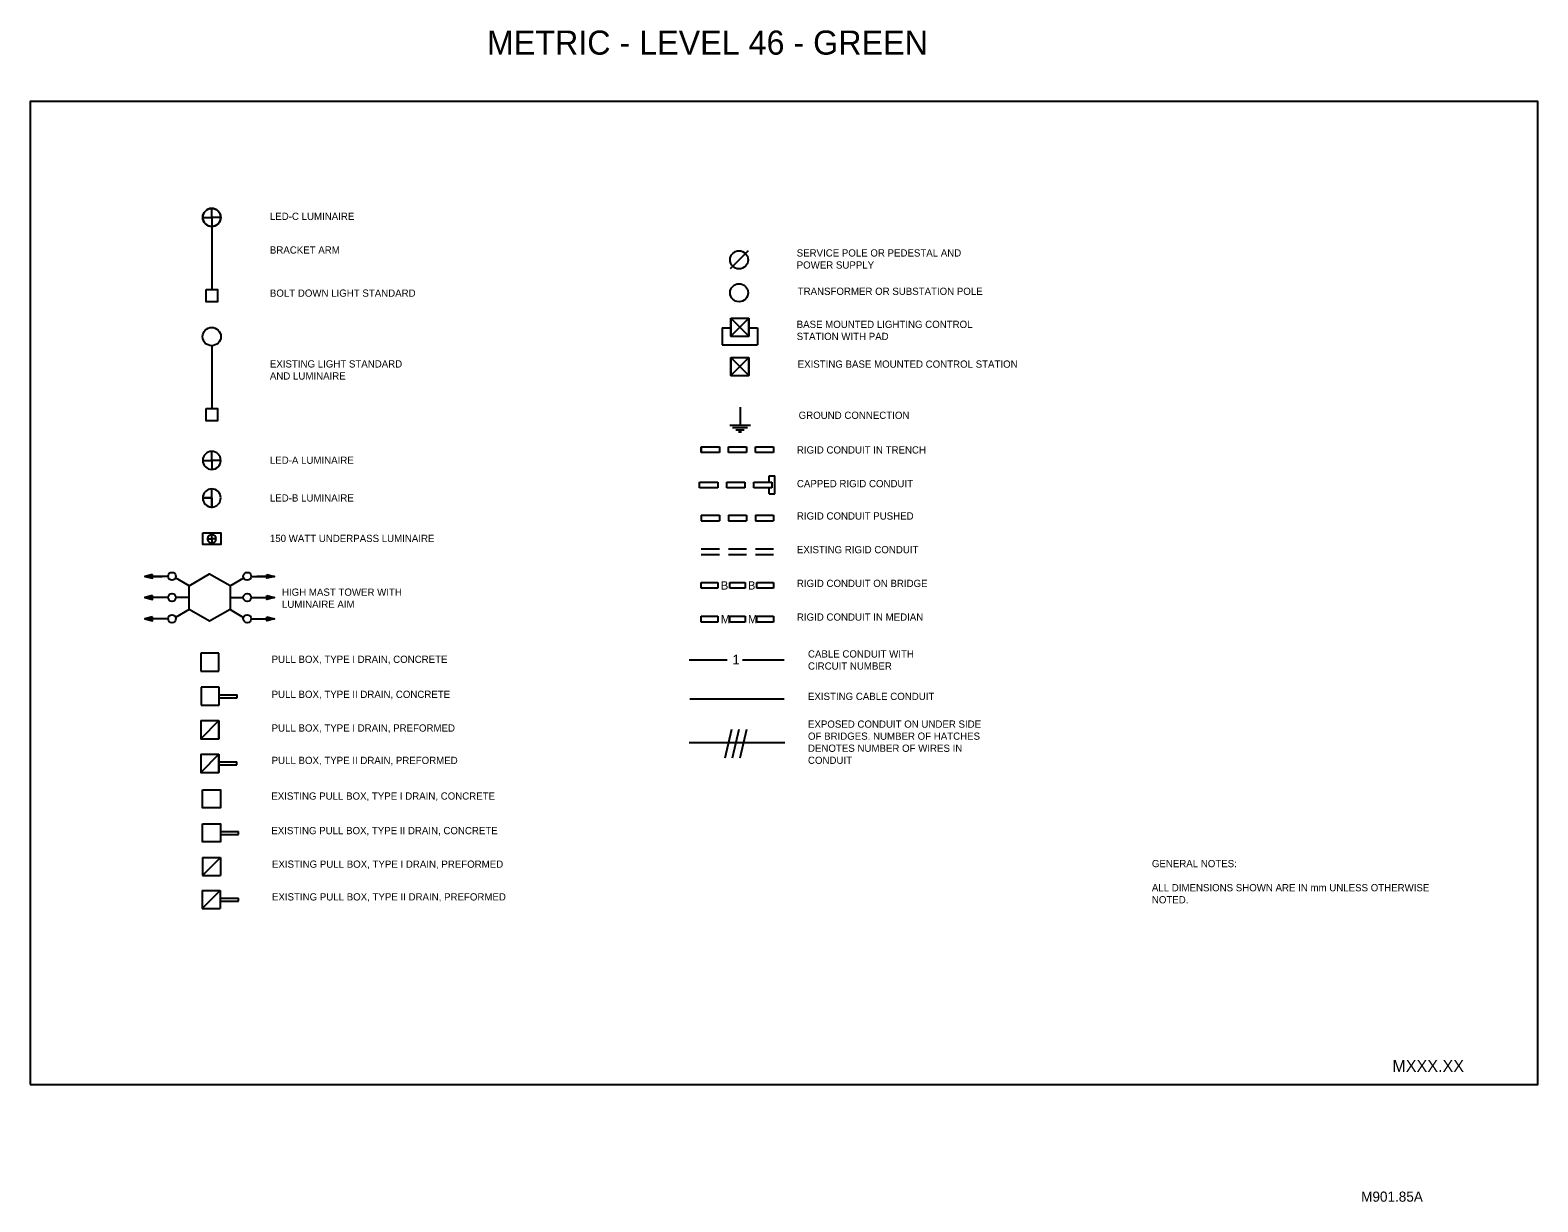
# Model space of a CAD drawing. Extents: x -439.1 to -407.9, y -460.5 to -436.2.
import ezdxf

# ---------------------------------------------------------------- set-up
doc = ezdxf.new("R2010")
doc.units = 0
for name, color, linetype in [('Draft_Named_Boundary', 7, 'Continuous'), ('Level 4', 7, 'Continuous'), ('Level 46', 7, 'Continuous')]:
    doc.layers.add(name, color=color, linetype=linetype)

msp = doc.modelspace()

# ---------------------------------------------------------------- linework, layer by layer
at = {"layer": 'Draft_Named_Boundary'}
msp.add_lwpolyline([(-439.109, -458.051), (-407.859, -458.051), (-407.859, -437.676), (-439.109, -437.676)], close=True, dxfattribs=at)
at = {"layer": 'Level 4'}
for p, q in [((-435.345, -440.079), (-435.345, -439.892)), ((-435.533, -440.079), (-435.345, -440.079)), ((-435.158, -440.079), (-435.345, -440.079)), ((-435.345, -440.079), (-435.345, -440.267)), ((-435.345, -440.079), (-435.345, -441.572)), ((-435.158, -440.079), (-435.158, -440.079)), ((-424.228, -440.77), (-424.602, -441.146)), ((-424.584, -442.169), (-424.584, -442.543)), ((-424.584, -442.169), (-424.21, -442.169)), ((-424.584, -442.169), (-424.21, -442.543)), ((-424.21, -442.169), (-424.584, -442.543)), ((-424.21, -442.169), (-424.21, -442.543)), ((-424.763, -442.366), (-424.763, -442.722)), ((-424.763, -442.366), (-424.584, -442.366)), ((-424.21, -442.366), (-424.031, -442.366)), ((-424.031, -442.366), (-424.031, -442.722)), ((-435.345, -442.738), (-435.345, -444.041)), ((-424.763, -442.722), (-424.031, -442.722)), ((-424.584, -442.543), (-424.21, -442.543)), ((-424.584, -442.982), (-424.584, -443.356)), ((-424.584, -442.982), (-424.21, -443.356)), ((-424.21, -442.982), (-424.584, -443.356)), ((-424.584, -442.982), (-424.21, -442.982)), ((-424.21, -442.982), (-424.21, -443.356)), ((-424.584, -443.356), (-424.21, -443.356)), ((-424.393, -444.015), (-424.393, -444.387)), ((-424.609, -444.387), (-424.177, -444.387)), ((-424.549, -444.435), (-424.243, -444.435)), ((-424.483, -444.483), (-424.309, -444.483)), ((-424.43, -444.526), (-424.363, -444.526)), ((-435.345, -445.115), (-435.345, -444.927)), ((-425.2, -444.833), (-425.2, -444.954)), ((-425.2, -444.954), (-425.2, -444.833)), ((-425.2, -444.954), (-425.2, -444.833)), ((-425.2, -444.833), (-424.824, -444.833)), ((-424.824, -444.954), (-425.2, -444.954)), ((-424.824, -444.833), (-424.824, -444.954)), ((-424.637, -444.954), (-424.637, -444.833)), ((-424.637, -444.833), (-424.262, -444.833)), ((-424.262, -444.954), (-424.637, -444.954)), ((-424.262, -444.833), (-424.262, -444.954)), ((-424.075, -444.954), (-424.075, -444.833)), ((-424.075, -444.833), (-423.7, -444.833)), ((-423.7, -444.954), (-424.075, -444.954)), ((-423.7, -444.833), (-423.7, -444.954)), ((-435.533, -445.115), (-435.345, -445.115)), ((-435.158, -445.115), (-435.345, -445.115)), ((-435.345, -445.115), (-435.345, -445.302)), ((-435.158, -445.115), (-435.158, -445.115)), ((-425.232, -445.684), (-425.232, -445.564)), ((-425.232, -445.564), (-424.857, -445.564)), ((-424.857, -445.564), (-424.857, -445.684)), ((-424.67, -445.684), (-424.67, -445.564)), ((-424.67, -445.564), (-424.294, -445.564)), ((-424.294, -445.564), (-424.294, -445.684)), ((-424.107, -445.684), (-424.107, -445.564)), ((-424.107, -445.564), (-423.733, -445.564)), ((-423.793, -445.437), (-423.673, -445.437)), ((-423.793, -445.564), (-423.793, -445.437)), ((-423.733, -445.564), (-423.733, -445.684)), ((-423.673, -445.811), (-423.673, -445.437)), ((-435.533, -445.894), (-435.345, -445.894)), ((-435.345, -445.894), (-435.345, -445.707)), ((-435.345, -445.894), (-435.345, -446.081)), ((-424.857, -445.684), (-425.232, -445.684)), ((-424.294, -445.684), (-424.67, -445.684)), ((-424.315, -445.684), (-424.295, -445.663)), ((-423.733, -445.684), (-424.107, -445.684)), ((-423.793, -445.811), (-423.793, -445.684)), ((-423.793, -445.811), (-423.673, -445.811)), ((-425.2, -446.248), (-425.2, -446.368)), ((-425.2, -446.248), (-424.824, -446.248)), ((-424.824, -446.248), (-424.824, -446.368)), ((-424.637, -446.248), (-424.637, -446.368)), ((-424.637, -446.248), (-424.262, -446.248)), ((-424.262, -446.248), (-424.262, -446.368)), ((-424.075, -446.248), (-424.075, -446.368)), ((-424.075, -446.248), (-423.7, -446.248)), ((-423.7, -446.248), (-423.7, -446.368)), ((-425.2, -446.368), (-424.824, -446.368)), ((-424.637, -446.368), (-424.262, -446.368)), ((-424.075, -446.368), (-423.7, -446.368)), ((-435.435, -446.739), (-435.345, -446.739)), ((-435.345, -446.739), (-435.345, -446.649)), ((-435.255, -446.739), (-435.345, -446.739)), ((-435.345, -446.739), (-435.345, -446.829)), ((-435.255, -446.739), (-435.255, -446.739)), ((-425.2, -446.947), (-424.824, -446.947)), ((-425.2, -447.067), (-424.824, -447.067)), ((-424.637, -446.947), (-424.262, -446.947)), ((-424.637, -447.067), (-424.262, -447.067)), ((-424.075, -446.947), (-423.7, -446.947)), ((-424.075, -447.067), (-423.7, -447.067)), ((-436.249, -447.519), (-436.733, -447.519)), ((-435.815, -447.712), (-436.097, -447.552)), ((-434.963, -447.712), (-434.682, -447.552)), ((-434.529, -447.519), (-434.046, -447.519)), ((-425.2, -447.767), (-425.2, -447.648)), ((-425.2, -447.648), (-424.855, -447.648)), ((-424.855, -447.767), (-425.2, -447.767)), ((-424.855, -447.648), (-424.855, -447.767)), ((-424.607, -447.767), (-424.607, -447.648)), ((-424.607, -447.648), (-424.292, -447.648)), ((-424.292, -447.767), (-424.607, -447.767)), ((-424.292, -447.648), (-424.292, -447.767)), ((-424.045, -447.767), (-424.045, -447.648)), ((-424.045, -447.648), (-423.7, -447.648)), ((-423.7, -447.767), (-424.045, -447.767)), ((-423.7, -447.648), (-423.7, -447.767)), ((-436.249, -447.957), (-436.733, -447.957)), ((-435.815, -447.958), (-436.08, -447.958)), ((-434.963, -447.958), (-434.698, -447.958)), ((-434.529, -447.957), (-434.046, -447.957)), ((-436.249, -448.399), (-436.733, -448.399)), ((-435.815, -448.203), (-436.093, -448.372)), ((-434.963, -448.203), (-434.686, -448.372)), ((-434.529, -448.399), (-434.046, -448.399)), ((-425.2, -448.466), (-425.2, -448.347)), ((-425.2, -448.347), (-424.855, -448.347)), ((-424.855, -448.347), (-424.855, -448.466)), ((-424.607, -448.466), (-424.607, -448.347)), ((-424.607, -448.347), (-424.292, -448.347)), ((-424.292, -448.347), (-424.292, -448.466)), ((-424.045, -448.466), (-424.045, -448.347)), ((-424.045, -448.347), (-423.7, -448.347)), ((-423.7, -448.347), (-423.7, -448.466)), ((-424.855, -448.466), (-425.2, -448.466)), ((-424.292, -448.466), (-424.607, -448.466)), ((-423.7, -448.466), (-424.045, -448.466)), ((-435.2, -449.111), (-435.574, -449.111)), ((-435.574, -449.111), (-435.574, -449.486)), ((-435.2, -449.486), (-435.2, -449.111)), ((-425.453, -449.246), (-424.659, -449.246)), ((-424.347, -449.246), (-423.482, -449.246)), ((-435.574, -449.486), (-435.2, -449.486)), ((-435.189, -449.817), (-435.565, -449.817)), ((-435.565, -449.817), (-435.565, -450.192)), ((-435.189, -450.192), (-435.189, -449.817)), ((-435.189, -449.974), (-434.815, -449.974)), ((-434.815, -450.034), (-434.815, -449.974)), ((-435.565, -450.192), (-435.189, -450.192)), ((-435.189, -450.034), (-434.815, -450.034)), ((-425.439, -450.055), (-423.482, -450.055)), ((-435.574, -450.51), (-435.574, -450.885)), ((-435.574, -450.51), (-435.2, -450.51)), ((-435.2, -450.51), (-435.574, -450.885)), ((-435.2, -450.51), (-435.2, -450.885)), ((-435.574, -450.885), (-435.2, -450.885)), ((-424.57, -450.694), (-424.711, -451.29)), ((-424.418, -450.694), (-424.559, -451.29)), ((-424.258, -450.694), (-424.399, -451.29)), ((-435.574, -451.206), (-435.574, -451.581)), ((-435.574, -451.206), (-435.198, -451.206)), ((-435.574, -451.581), (-435.198, -451.206)), ((-435.198, -451.206), (-435.198, -451.581)), ((-425.453, -450.963), (-423.467, -450.963)), ((-435.198, -451.363), (-434.824, -451.363)), ((-435.198, -451.423), (-434.824, -451.423)), ((-434.824, -451.423), (-434.824, -451.363)), ((-435.574, -451.581), (-435.198, -451.581)), ((-435.162, -452.808), (-434.788, -452.808)), ((-434.788, -452.868), (-434.788, -452.808)), ((-435.162, -452.868), (-434.788, -452.868)), ((-435.538, -453.344), (-435.538, -453.718)), ((-435.538, -453.344), (-435.164, -453.344)), ((-435.164, -453.344), (-435.538, -453.718)), ((-435.164, -453.344), (-435.164, -453.718)), ((-435.538, -453.718), (-435.164, -453.718)), ((-435.543, -454.03), (-435.543, -454.405)), ((-435.543, -454.03), (-435.168, -454.03)), ((-435.543, -454.405), (-435.168, -454.03)), ((-435.168, -454.03), (-435.168, -454.405)), ((-435.168, -454.188), (-434.794, -454.188)), ((-435.168, -454.248), (-434.794, -454.248)), ((-434.794, -454.248), (-434.794, -454.188)), ((-435.543, -454.405), (-435.168, -454.405))]:
    msp.add_line(p, q, dxfattribs=at)
for points in [[(-435.46, -441.572), (-435.229, -441.572), (-435.229, -441.826), (-435.46, -441.826)], [(-424.584, -442.169), (-424.396, -442.357), (-424.584, -442.543)], [(-424.21, -442.169), (-424.396, -442.357), (-424.21, -442.543)], [(-424.584, -442.982), (-424.396, -443.17), (-424.584, -443.356)], [(-424.21, -442.982), (-424.396, -443.17), (-424.21, -443.356)], [(-435.46, -444.041), (-435.229, -444.041), (-435.229, -444.296), (-435.46, -444.296)], [(-435.345, -445.894), (-435.533, -445.894), (-435.531, -445.923), (-435.525, -445.946), (-435.518, -445.966), (-435.505, -445.992), (-435.488, -446.015), (-435.469, -446.035), (-435.444, -446.053), (-435.414, -446.069), (-435.38, -446.078), (-435.345, -446.081)], [(-435.531, -446.619), (-435.158, -446.619), (-435.158, -446.857), (-435.531, -446.857)], [(-436.576, -447.48), (-436.733, -447.519), (-436.576, -447.559)], [(-434.963, -448.203), (-435.389, -448.449), (-435.815, -448.203), (-435.815, -447.712), (-435.389, -447.465), (-434.963, -447.711)], [(-434.202, -447.48), (-434.046, -447.519), (-434.202, -447.559)], [(-436.576, -447.918), (-436.733, -447.957), (-436.576, -447.997)], [(-434.202, -447.918), (-434.046, -447.957), (-434.202, -447.997)], [(-436.576, -448.36), (-436.733, -448.399), (-436.576, -448.438)], [(-434.202, -448.36), (-434.046, -448.399), (-434.202, -448.438)], [(-435.2, -450.51), (-435.574, -450.885), (-435.2, -450.885)], [(-435.198, -451.206), (-435.574, -451.581), (-435.198, -451.581)], [(-435.538, -451.944), (-435.164, -451.944), (-435.164, -452.319), (-435.538, -452.319)], [(-435.537, -452.65), (-435.162, -452.65), (-435.162, -453.025), (-435.537, -453.025)]]:
    msp.add_lwpolyline(points, close=True, dxfattribs=at)
for points in [[(-436.733, -447.519), (-436.537, -447.519), (-436.37, -447.519)], [(-434.046, -447.519), (-434.241, -447.519), (-434.408, -447.519)]]:
    msp.add_lwpolyline(points, dxfattribs=at)
for centre, radius in [((-435.345, -440.079), 0.188), ((-424.415, -440.958), 0.187), ((-424.415, -441.641), 0.187), ((-435.345, -442.549), 0.189), ((-436.169, -447.518), 0.0824), ((-434.61, -447.518), 0.0824), ((-436.169, -447.957), 0.0824), ((-434.61, -447.957), 0.0824), ((-436.169, -448.397), 0.0824), ((-434.61, -448.397), 0.0824)]:
    msp.add_circle(centre, radius, dxfattribs=at)
for centre, radius, start, end in [((-435.345, -440.079), 0.187, 89.9559, 179.9354), ((-435.345, -440.079), 0.187, 0.0646, 89.9559), ((-435.345, -440.079), 0.187, 179.9366, 270.0444), ((-435.345, -440.079), 0.187, 270.0444, 0.0635), ((-435.345, -445.115), 0.187, 89.9559, 179.9354), ((-435.345, -445.115), 0.187, 0.0646, 89.9559), ((-435.345, -445.115), 0.187, 179.9366, 270.0444), ((-435.345, -445.115), 0.187, 270.0444, 0.0635), ((-435.345, -445.894), 0.187, 89.9559, 179.9354), ((-435.345, -445.894), 0.187, 179.9366, 270.0444), ((-435.345, -445.895), 0.187, 208.5324, 0.2174), ((-435.345, -445.894), 0.187, 0.0646, 89.9559), ((-435.345, -446.739), 0.0896, 89.9559, 179.9354), ((-435.345, -446.739), 0.0896, 179.9366, 270.0444), ((-435.345, -446.739), 0.0896, 0.0646, 89.9559), ((-435.345, -446.739), 0.0896, 270.0444, 0.0635)]:
    msp.add_arc(centre, radius, start, end, dxfattribs=at)

# ---------------------------------------------------------------- texts
for s, height, p in [('LED-C LUMINAIRE', 0.15, (-434.14, -440.131)), ('BRACKET ARM', 0.15, (-434.14, -440.829)), ('SERVICE POLE OR PEDESTAL AND', 0.15, (-423.221, -440.89)), ('POWER SUPPLY', 0.15, (-423.221, -441.14)), ('TRANSFORMER OR SUBSTATION POLE', 0.15, (-423.2, -441.685)), ('BOLT DOWN LIGHT STANDARD', 0.15, (-434.14, -441.723)), ('STATION WITH PAD', 0.15, (-423.221, -442.62)), ('BASE MOUNTED LIGHTING CONTROL', 0.15, (-423.221, -442.37)), ('EXISTING LIGHT STANDARD', 0.15, (-434.14, -443.19)), ('EXISTING BASE MOUNTED CONTROL STATION', 0.15, (-423.2, -443.194)), ('AND LUMINAIRE', 0.15, (-434.14, -443.44)), ('GROUND CONNECTION', 0.15, (-423.18, -444.255)), ('RIGID CONDUIT IN TRENCH', 0.15, (-423.216, -444.973)), ('LED-A LUMINAIRE', 0.15, (-434.14, -445.186)), ('CAPPED RIGID CONDUIT', 0.15, (-423.216, -445.672)), ('LED-B LUMINAIRE', 0.15, (-434.14, -445.969)), ('RIGID CONDUIT PUSHED', 0.15, (-423.216, -446.342)), ('150 WATT UNDERPASS LUMINAIRE', 0.15, (-434.14, -446.807)), ('EXISTING RIGID CONDUIT', 0.15, (-423.216, -447.04)), ('HIGH MAST TOWER WITH', 0.15, (-433.889, -447.921)), ('B', 0.171, (-424.792, -447.793)), ('B', 0.171, (-424.23, -447.793)), ('RIGID CONDUIT ON BRIDGE', 0.15, (-423.216, -447.739)), ('LUMINAIRE AIM', 0.15, (-433.889, -448.171)), ('M', 0.171, (-424.792, -448.492)), ('M', 0.171, (-424.23, -448.492)), ('RIGID CONDUIT IN MEDIAN', 0.15, (-423.216, -448.437)), ('CABLE CONDUIT WITH', 0.15, (-422.987, -449.202)), ('PULL BOX, TYPE I DRAIN, CONCRETE', 0.15, (-434.104, -449.313)), ('1', 0.2, (-424.552, -449.344)), ('CIRCUIT NUMBER', 0.15, (-422.987, -449.452)), ('PULL BOX, TYPE II DRAIN, CONCRETE', 0.15, (-434.104, -450.039)), ('EXISTING CABLE CONDUIT', 0.15, (-422.987, -450.081)), ('PULL BOX, TYPE I DRAIN, PREFORMED', 0.15, (-434.104, -450.737)), ('EXPOSED CONDUIT ON UNDER SIDE', 0.15, (-422.987, -450.656)), ('OF BRIDGES. NUMBER OF HATCHES', 0.15, (-422.987, -450.906)), ('DENOTES NUMBER OF WIRES IN', 0.15, (-422.987, -451.156)), ('PULL BOX, TYPE II DRAIN, PREFORMED', 0.15, (-434.104, -451.408)), ('CONDUIT', 0.15, (-422.987, -451.406)), ('EXISTING PULL BOX, TYPE I DRAIN, CONCRETE', 0.15, (-434.11, -452.147)), ('EXISTING PULL BOX, TYPE II DRAIN, CONCRETE', 0.15, (-434.11, -452.864)), ('EXISTING PULL BOX, TYPE I DRAIN, PREFORMED', 0.15, (-434.097, -453.559)), ('EXISTING PULL BOX, TYPE II DRAIN, PREFORMED', 0.15, (-434.097, -454.237))]:
    msp.add_text(s, height=height, dxfattribs=at).set_placement(p)
at = {"layer": 'Level 46'}
for s, height, p in [('METRIC - LEVEL 46 - GREEN', 0.5, (-429.642, -436.705)), ('GENERAL NOTES:', 0.15, (-415.859, -453.547)), ('ALL DIMENSIONS SHOWN ARE IN mm UNLESS OTHERWISE ', 0.15, (-415.859, -454.047)), ('NOTED.', 0.15, (-415.859, -454.297)), ('MXXX.XX', 0.25, (-410.875, -457.792)), ('M901.85A', 0.21, (-411.522, -460.481))]:
    msp.add_text(s, height=height, dxfattribs=at).set_placement(p)

doc.saveas('drawing.dxf')
